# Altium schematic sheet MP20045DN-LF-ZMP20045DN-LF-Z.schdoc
size 127 x 101 mm
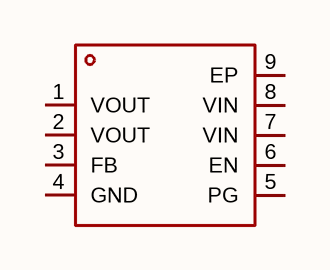
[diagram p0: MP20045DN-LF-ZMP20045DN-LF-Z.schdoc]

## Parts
U?  mp20045dn-lf-z  [SOIC-8_L4.9-W3.9-P1.27-LS6.0-TL-EP-2]  (value not drawn)

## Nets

Not connected (* = marked no-connect by the designer): U? 1(VOUT) 2(VOUT) 3(FB) 4(GND) 5(PG) 6(EN) 7(VIN) 8(VIN) 9(EP)

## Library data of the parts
U? = mp20045dn-lf-z: 输出极性:正极;工作电压:5.5V;输出电压:1.5V~5V;输出电流:1A;电源纹波抑制比(PSRR):56dB;输出类型:可调;; Manufacturer: MPS(芯源); AddInBom: yes; ModelId: 720dfcfd3a924bbcb9284cc69a02128f; ModelTransform: 236.22,192.913,0,0,0,0,0,0,0; Output Configuration: 正极; Voltage - Supply: 5.5V; Output Current: 1A; Power Supply Rejection Ratio (PSRR): 56dB; Voltage Dropout: 140mV@(1A); standby current: 110uA; Noise: 13uVrms; Output Type: 可调; Number of Outputs: 1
